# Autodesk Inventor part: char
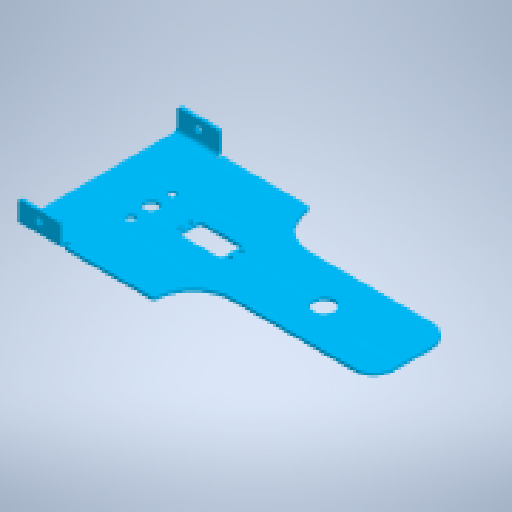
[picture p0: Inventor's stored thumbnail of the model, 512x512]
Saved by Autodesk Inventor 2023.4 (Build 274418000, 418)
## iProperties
Created: 2023-11
Part Number: char
Material: Plastique PMMA
Document SubType Name: Sheet Metal
Designer: mel
Density: 1.188 g/cm^3
Flat Pattern Width: 30 cm
Flat Pattern Length: 19 cm
Flat Pattern Area: 570 cm^2
Sheet Metal Rule: Par défaut_mm
Sheet Metal Width: 300,000 mm
Sheet Metal Length: 190,000 mm
Sheet Metal Area: 57000,000 mm^2
Appearance: Bleu ciel moyen
Author: mel
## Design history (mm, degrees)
node "Face1"
  sketch "Esquisse1"
    geometry: L1 (-173.971, -2.5)-(-261.25, -2.5); L2 (-301.25, 2.5)-(-301.25, 152.5); L3 (-261.25, 147.5)-(-173.971, 147.5); L4 (-1.25, 91.25)-(-1.25, 53.75); L5 (-136.471, 110)-(-20, 110); L6 (-1.25, 91.25)-(-1.25, 53.75); L7 (-20, 35)-(-136.471, 35); L8 (-261.25, 147.5)-(-261.25, 167.5); L9 (-261.25, 167.5)-(-301.25, 167.5); L10 (-301.25, 167.5)-(-301.25, 152.5); L11 (-261.25, -2.5)-(-261.25, -22.5); L12 (-261.25, -22.5)-(-301.25, -22.5); L13 (-301.25, -22.5)-(-301.25, 2.5); A1 r 37.5 centre (-136.471, 147.5) between (-173.971, 147.5) and (-136.471, 110); A2 r 37.5 centre (-136.471, -2.5) between (-136.471, 35) and (-173.971, -2.5); A3 r 18.75 centre (-20, 91.25) between (-1.25, 91.25) and (-20, 110); A4 r 18.75 centre (-20, 53.75) between (-20, 35) and (-1.25, 53.75); 4 further points
    constraints: 26 end point, 8 point on circle, 6 point on line, 6 tangent, 5 parallel, 4 centre point, 2 horizontal, 2 perpendicular, 1 equal radius, 1 midpoint
    dimensions: "d1" = 300 distance from line of point (-301.25, 77.5) L4; "d2" = 150 distance between parallel lines of L1 L3; "d3" = 75 diameter of A1; "d4" = 75 diameter of A2 (= d3); "d5" = 18.75 radius of A3 (= 0.25 x d3); "d6" = 40 distance of L9.end L8.end; "d7" = 20 distance of L3.start L8.end; "d8" = 40 distance between parallel lines of L11 L13 (= d6); "d9" = 20 distance between parallel lines of L12 L1 (= d7)
sketch "Esquisse3"
  geometry: L1 (-261.25, 147.5)-(-301.25, 147.5); L2 (-301.25, -22.5)-(-301.25, 167.5) reference; 1 further point
  constraints: 2 end point, 1 horizontal, 1 point on line
feature "Pliage1" sketch "Esquisse3" dims "d0" = 3 (= Epaisseur), "d10" = 3 (= LargeurGrugeage), "d11" = 1.5 (= ProfondeurGrugeage), "d12" = 6 (= RestesMinimum), "d13" = 3 (= Rayondetransition), "d14" = 90 deg, "d15" = 3 (= RayonPli), "SeamGap" = 0.01
sketch "Esquisse4"
  geometry: L1 (-124.779, -37.5)-(-37.5, -37.5) reference; L2 (-124.779, -37.5)-(-164.779, -37.5); L3 (-164.779, -57.5)-(-164.779, 109.107) reference; 1 further point
  constraints: 2 end point, 1 horizontal, 1 point on line
feature "Pliage2" sketch "Esquisse4" dims "d0" = 3 (= Epaisseur), "d16" = 3 (= LargeurGrugeage), "d17" = 1.5 (= ProfondeurGrugeage), "d18" = 6 (= RestesMinimum), "d19" = 3 (= Rayondetransition), "d20" = 90 deg, "d21" = 3 (= RayonPli), "SeamGap" = 0.01
sketch "Esquisse5"
  geometry: L1 (261.25, 167.5)-(301.25, 167.5) reference; 2 further points
  dimensions: "d22" = 9 distance from line of L1 point (281.25, 158.5)
hole "Perçage1" sketch "Esquisse5" at (281.25, 158.5) diameter "d23" = 6; stored, may be unused: countersink angle "d27" = 90 deg, drill point angle "d29" = 118 deg; dims "d24" = 6, "d25" = 4, "d26" = 2, "d28" = 3 (= Epaisseur)
fillet "Congé1" dims "d30" = 3
sketch "Esquisse6"
  geometry: L1 (-121.779, 112.5)-(-40.389, 112.5) reference; L2 (-164.779, -34.107)-(-164.779, 109.107) reference; C1 r 6.75 at (-114.779, 37.5); 1 further point
  constraints: 1 centre point
  dimensions: "d31" = 75 distance from line of C1.centre L1; "d32" = 50 distance from line of C1.centre L2; "d33" = 13.5 diameter of C1
extrude "Extrusion1" cut sketch "Esquisse6" extent not by distance; stored distance "d34" = 0; taper "d35" = 0 deg
sketch "Esquisse7"
  geometry: C1 r 2.5 at (-114.779, 17.5) reference; C2 r 2.5 at (-114.779, 57.5) reference; 1 further point
hole "Perçage2" sketch "Esquisse7" at (-114.779, 57.5), (-114.779, 17.5) diameter "d36" = 8.1; stored, may be unused: countersink angle "d40" = 90 deg, drill point angle "d42" = 118 deg; dims "d37" = 6, "d38" = 4, "d39" = 2, "d41" = 8
extrude "Extrusion2" cut sketch "Esquisse8" extent not by distance; stored distance "d44" = 0; taper "d45" = 0 deg
sketch "Esquisse9"
  geometry: L1 (135.221, 56.25)-(135.221, 18.75) reference; C1 r 10 at (50.221, 37.5); 1 further point
  constraints: 1 centre point
  dimensions: "d46" = 20 diameter of C1; "d47" = 85 distance from line of L1 C1.centre
hole "Perçage3" sketch "Esquisse9" at (50.221, 37.5) diameter "d48" = 20; stored, may be unused: countersink angle "d52" = 90 deg, drill point angle "d54" = 0 deg; dims "d49" = 6, "d50" = 4, "d51" = 2, "d53" = 3 (= Epaisseur)
node "Solide1"
feature "Plaque1" dims "d0" = 3 (= Epaisseur)
node "Référence1"
node "Référence2"
feature "Définition1"
feature "耀䀦"
other parameters: "Epaisseur" = 3 (derived), "RayonPli" = 3 (= Epaisseur), "LargeurGrugeage" = 3 (= Epaisseur), "ProfondeurGrugeage" = 1.5 (= 0.5 x Epaisseur), "TailleGrugeage" = 12 (= 4 x Epaisseur), "RestesMinimum" = 6 (= 2 x Epaisseur), "Rayondetransition" = 3 (= RayonPli), "TailleRayonJacobi" = 3 (= RayonPli), "TailleJeu" = 3 (= Epaisseur), "d43" = 0.5, "Epaisseur" = 3, "LargeurGrugeage" = 3, "ProfondeurGrugeage" = 1.5, "RayonPli" = 3, "Rayondetransition" = 3, "RestesMinimum" = 6, "TailleGrugeage" = 12, "TailleJeu" = 3, "TailleRayonJacobi" = 3
